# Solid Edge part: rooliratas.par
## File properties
Author: Mac
Template: Normal.par
Last saved by: Mac
Revision: 2
Application: Solid Edge
Density: 600,000 kg/m^3
Accuracy: 0,990
Material: Wood, Mahogany
Face Style: Tan
Fill Style: Cork
Virtual Style: Polished mahogany
Coef. of Thermal Exp: 0.0
Thermal Conductivity: 0.0
Specific Heat: 0.0
Modulus of Elasticity: 0.0
Poission's Ratio: 0.0
Yield Stress: 0.0
Ultimate Stress: 0.0
Elongation: 0.0
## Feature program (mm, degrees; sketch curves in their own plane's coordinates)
swept protrusion "unnamed SweptProtrusion 1"
sketch for "ExtrudedProtrusion_1" plane through (0.0055, -0.7161, 0) normal (-1.5e-05, 1, -0.00098) x-axis (-1, -1.5e-05, 0)
extrude "ExtrudedProtrusion_1" add finite 0.06 along +normal
sketch for "ExtrudedCutout_1" #1 plane through (0, -0.5803, 0) normal (0, -1, 0) x-axis (1, 0, 0)
  bspline degree 3 poles (-3.8183, -2.9279) (-1.3018, -1.427) (1.2562, -1.427) (3.8292, -2.9279) knots 0 1 multiplicities 4 4
  arc centre (0.0055, 0) radius 4.816 from (4.0055, -2.6821) to (3.8292, -2.9279) cw
  bspline degree 3 poles (4.0055, 2.6821) (-0.201, 1.1221) (1.0645, -1.1978) (4.0055, -2.6821) knots 0 1 multiplicities 4 4
  arc centre (0.0055, 0) radius 4.816 from (3.4625, 3.353) to (4.0055, 2.6821) cw
  bspline degree 3 poles (-3.4516, 3.353) (-1.165, 1.8271) (1.1476, 1.8271) (3.4625, 3.353) knots 0 1 multiplicities 4 4
  bspline degree 3 poles (-3.9945, 2.6821) (0.2119, 1.1221) (-1.0536, -1.1978) (-3.9945, -2.6821) knots 0 1 multiplicities 4 4
  arc centre (0.0055, 0) radius 4.816 from (-3.8183, -2.9279) to (-3.9945, -2.6821) cw
sketch for "ExtrudedCutout_1" #2 plane through (0, -0.5803, 0) normal (0, -1, 0) x-axis (1, 0, 0)
  circle centre (0.0055, 0) radius 6.3986
extrude "ExtrudedCutout_1" cut finite 12.2 symmetric
sketch for "unnamed RevolvedProtrusion 1" plane through (0, 0, 0) normal (0, 0, 1) x-axis (1, 0, 0)
  circle centre (4.8, 0) radius 0.3
revolve "unnamed RevolvedProtrusion 1" add full turn 360 deg
sketch for "unnamed Cutout 1" plane through (0.0055, -0.6561, -0.0002) normal (-1.5e-05, 1, -0.00098) x-axis (-1, -1.5e-05, 0)
extrude "unnamed Cutout 1" cut through along -normal
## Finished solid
Body 1: solid body, 26 faces, 68 edges, 40 vertices.
  Faces by surface: spline 12, cylinder 6, swept 4, plane 3, torus 1
  Edges by curve: intersection 52, spline 8, circle 4, line 4
Bounding box of the edges (mm; curved faces can reach further): 7.460 x 0.779 x 5.961, from (-3.7281, -0.7773, -2.7765) to (3.7314, 0.0019, 3.1842).
Cylindrical faces by radius (mm): R0.1 x1, R0.6 x1, R12.3427 x2, R12.4027 x2
Toroidal faces (ring radius, tube radius in mm): R4.8 r0.3 x1
Planar faces by outward normal: +y 2, -y 1
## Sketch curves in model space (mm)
spline (1.0055, -0.8167, 0) -> (2.9086, -0.5517, 0) -> (4.8097, -0.0283, 0)
line (-0.9946, -0.8167, 0) -> (1.0055, -0.8167, 0)
spline (-4.8097, -0.0284, 0) -> (-2.9014, -0.5518, 0) -> (-0.9946, -0.8167, 0)
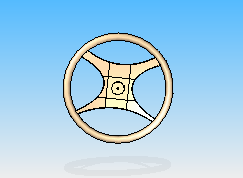
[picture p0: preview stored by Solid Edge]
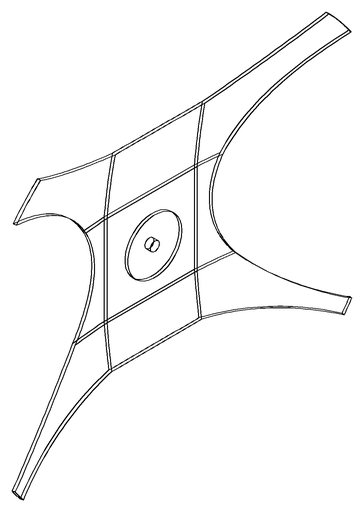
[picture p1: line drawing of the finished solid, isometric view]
